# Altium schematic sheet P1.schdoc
size 594 x 419 mm; Symbol: Drawing-Symbol_A4; Company: 嘉立创EDA; Version: V1.0; Page Size: A4; @Project Name: mairui N1; @Update Date: 2026-05-10; @Create Date: 2026-05-10; Device: Drawing-Symbol_A4; @Board Name: 底板_2; @Page Name: P1; @Create Time: 14:56:52; @Page Count: 6; @Page No: 6; @Schematic Name: Bottom_4; @Update Time: 14:56:52; @Assembly Variant: Basic; Border: 1; Title Block Position: 3; Size: A4; Width: 2338; Height: 1652; Region Start: 1; X Region Count: 6; Y Region Count: 4; Blade Width: 10
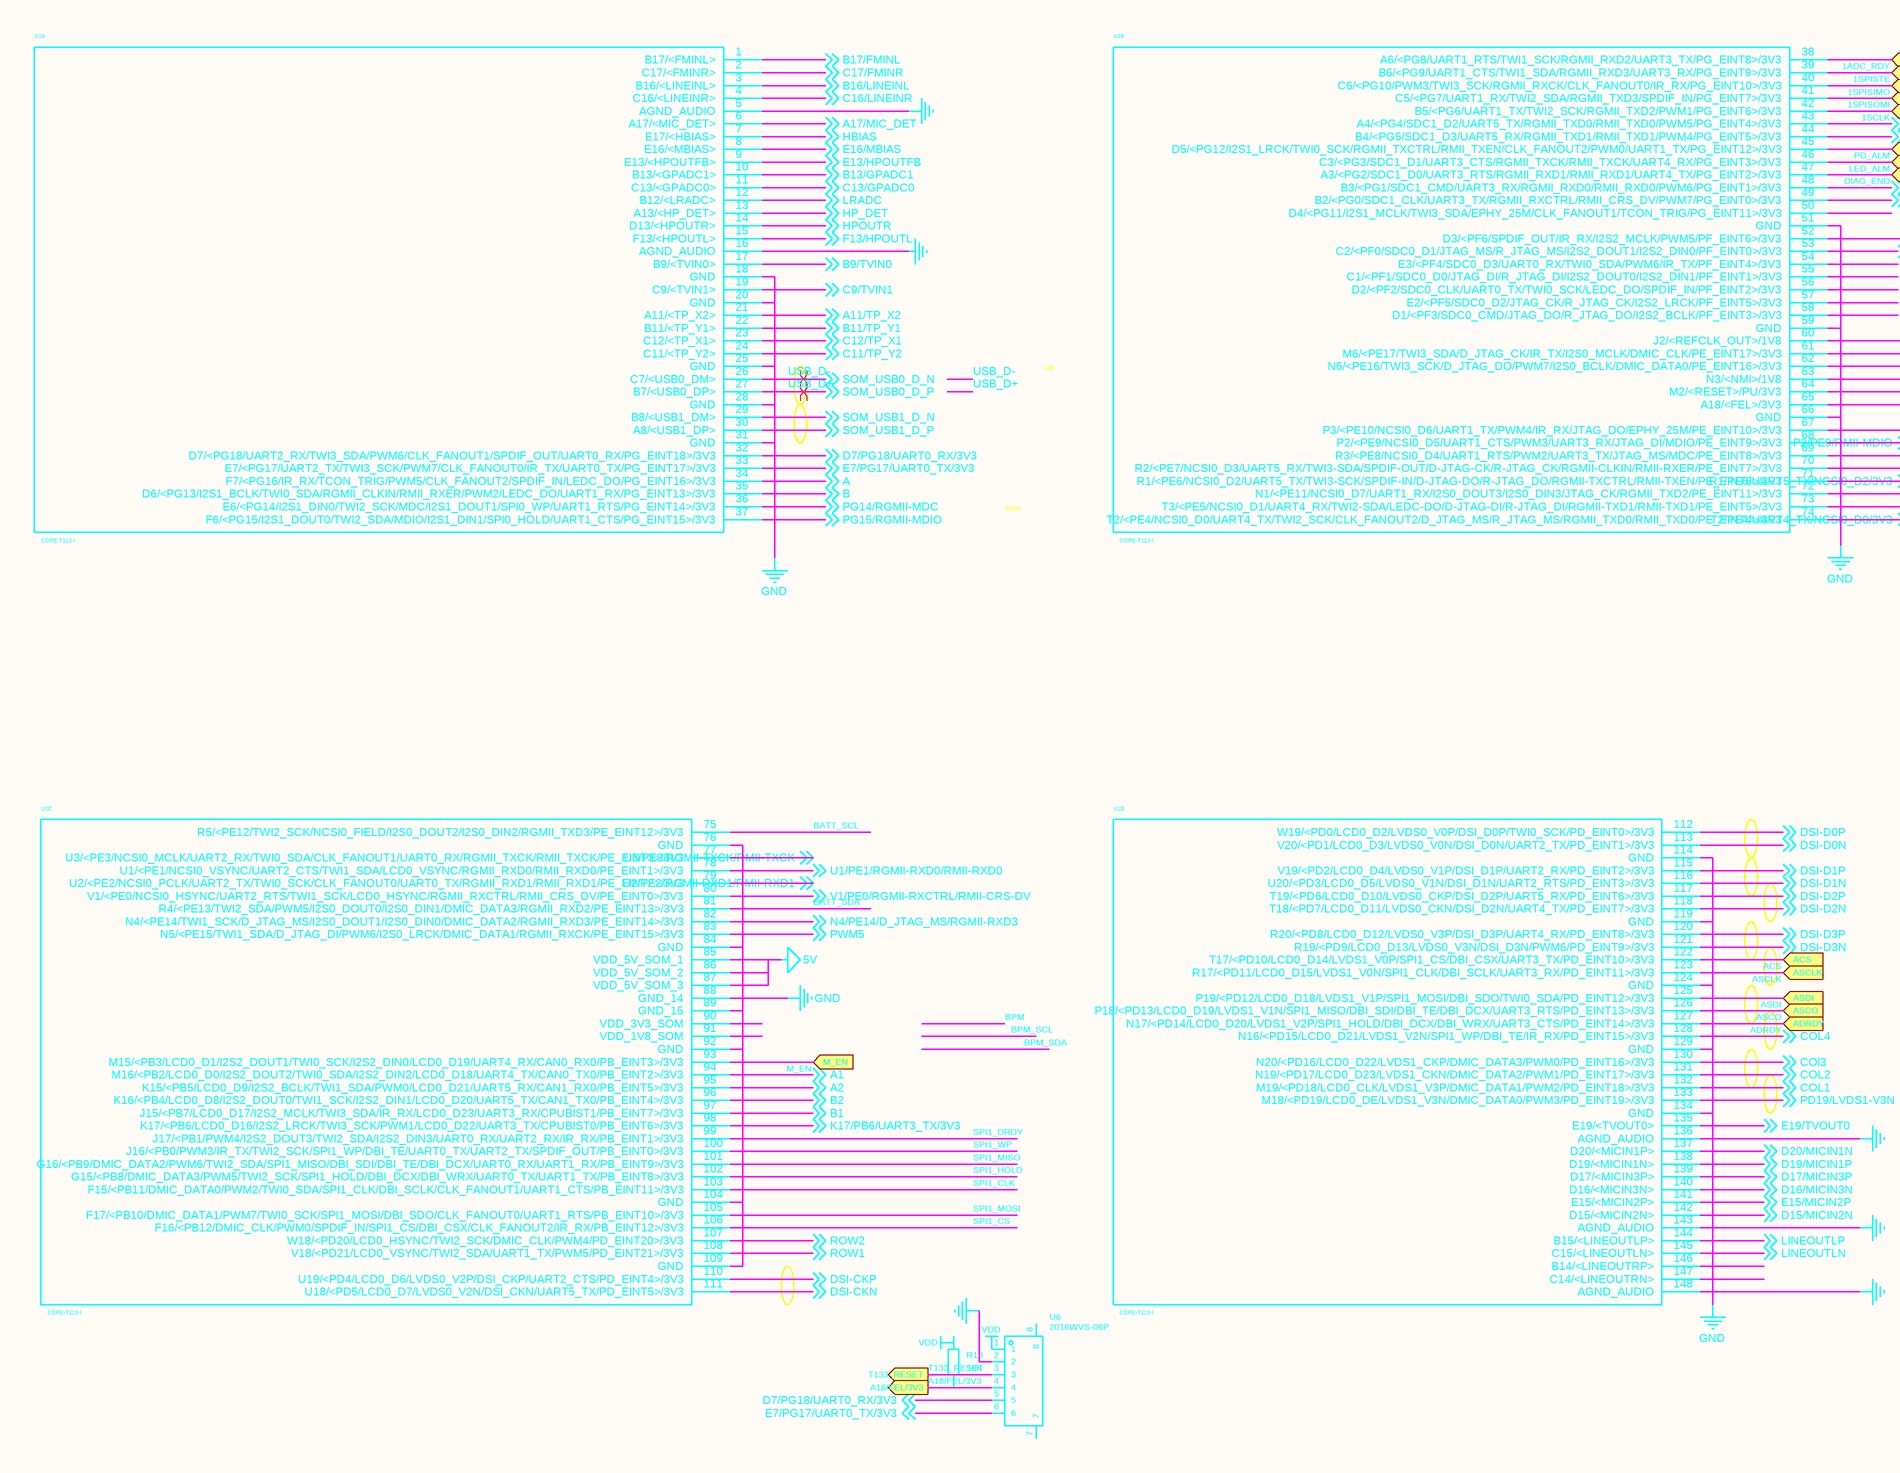
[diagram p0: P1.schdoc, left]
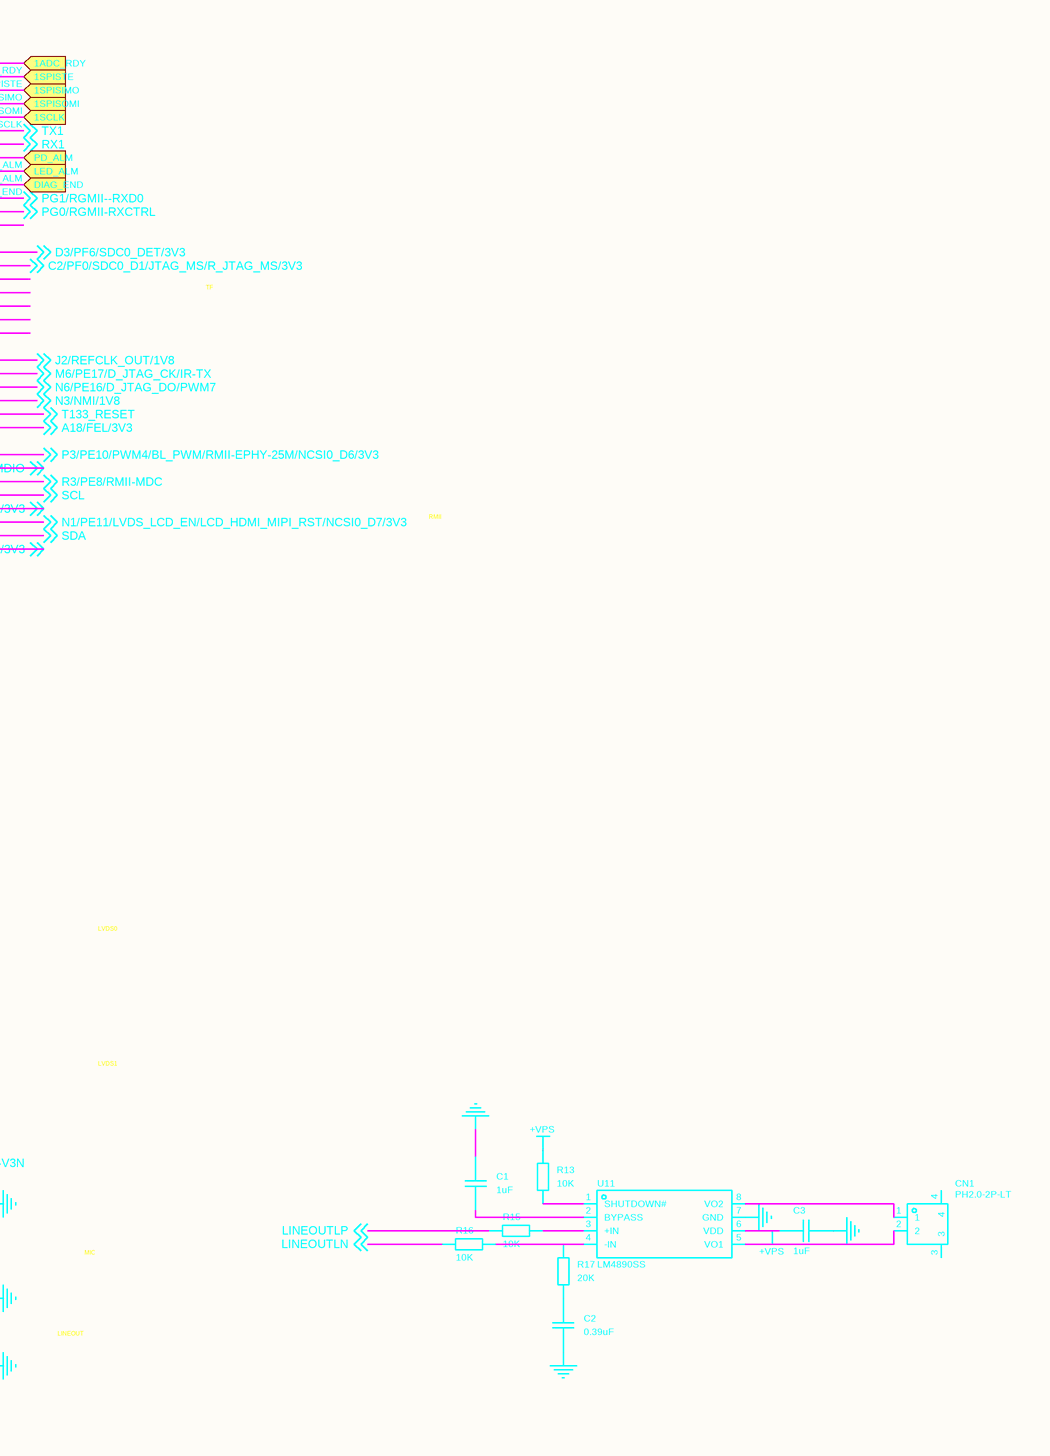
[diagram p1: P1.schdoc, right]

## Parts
C1  1uF  [C0603]
C2  0.39uF  [C0603]
C3  1uF  [C0603]
CN1  PH2.0-2P-LT  [CONN-SMD_PH2.0-1X2PW]
R13  10K  [R0603]
R15  10K  [R0603]
R16  10K  [R0603]
R17  20K  [R0603]
R18  10K  [R0603]
U1  CORE-T113-I  [CORE-40X40-TAP148]  (parts A,B,C,D of 4)
U6  2016WVS-06P  [CONN-SMD_2016WVS-06P]
U11  LM4890SS  [MSOP-8_L3.0-W3.0-P0.65-LS4.9-BL-1]

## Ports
1ADC_RDY (in), 1SCLK (in), 1SPISIMO (in), 1SPISOMI (in), 1SPISTE (in), A18/FEL/3V3 (out), ACS (in), ADRDY (in), ASCLK (in), ASCO (in), ASDI (in), DIAG_END (in), LED_ALM (in), M_EN (in), PD_ALM (in), T133_RESET (out)

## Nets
5V: U1.85(VDD_5V_SOM_1) U1.86(VDD_5V_SOM_2) U1.87(VDD_5V_SOM_3)
+VPS: C3.2 R13.2 U11.6(VDD)
GND: C1.2 C2.2 C3.1 U1.5(AGND_AUDIO) U1.16(AGND_AUDIO) U1.18(GND) U1.20(GND) U1.25(GND) U1.28(GND) U1.31(GND) U1.51(GND) U1.59(GND) U1.66(GND) U1.76(GND) U1.84(GND) U1.88(GND_14) U1.89(GND_15) U1.92(GND) U1.104(GND) U1.109(GND) U1.114(GND) U1.119(GND) U1.124(GND) U1.129(GND) U1.134(GND) U1.136(AGND_AUDIO) U1.143(AGND_AUDIO) U1.148(AGND_AUDIO) U6.2 U11.7(GND)
VDD: U6.1
1ADC_RDY: U1.38(A6/<PG8/UART1_RTS/TWI1_SCK/RGMII_RXD2/UART3_TX/PG_EINT8>/3V3) ; port 1ADC_RDY
1SCLK: U1.42(B5/<PG6/UART1_TX/TWI2_SCK/RGMII_TXD2/PWM1/PG_EINT6>/3V3) ; port 1SCLK
1SPISIMO: U1.40(C6/<PG10/PWM3/TWI3_SCK/RGMII_RXCK/CLK_FANOUT0/IR_RX/PG_EINT10>/3V3) ; port 1SPISIMO
1SPISOMI: U1.41(C5/<PG7/UART1_RX/TWI2_SDA/RGMII_TXD3/SPDIF_IN/PG_EINT7>/3V3) ; port 1SPISOMI
1SPISTE: U1.39(B6/<PG9/UART1_CTS/TWI1_SDA/RGMII_RXD3/UART3_RX/PG_EINT9>/3V3) ; port 1SPISTE
A: U1.34(F7/<PG16/IR_RX/TCON_TRIG/PWM5/CLK_FANOUT2/SPDIF_IN/LEDC_DO/PG_EINT16>/3V3) ; off-sheet A
A1: U1.94(M16/<PB2/LCD0_D0/I2S2_DOUT2/TWI0_SDA/I2S2_DIN2/LCD0_D18/UART4_TX/CAN0_TX0/PB_EINT2>/3V3) ; off-sheet A1
A2: U1.95(K15/<PB5/LCD0_D9/I2S2_BCLK/TWI1_SDA/PWM0/LCD0_D21/UART5_RX/CAN1_RX0/PB_EINT5>/3V3) ; off-sheet A2
A11/TP_X2: U1.21(A11/<TP_X2>) ; off-sheet A11/TP_X2
A17/MIC_DET: U1.6(A17/<MIC_DET>) ; off-sheet A17/MIC_DET
A18/FEL/3V3: R18.1 U1.65(A18/<FEL>/3V3) U6.4 ; off-sheet A18/FEL/3V3, port A18/FEL/3V3
ACS: U1.122(T17/<PD10/LCD0_D14/LVDS1_V0P/SPI1_CS/DBI_CSX/UART3_TX/PD_EINT10>/3V3) ; port ACS
ADRDY: U1.127(N17/<PD14/LCD0_D20/LVDS1_V2P/SPI1_HOLD/DBI_DCX/DBI_WRX/UART3_CTS/PD_EINT14>/3V3) ; port ADRDY
ASCLK: U1.123(R17/<PD11/LCD0_D15/LVDS1_V0N/SPI1_CLK/DBI_SCLK/UART3_RX/PD_EINT11>/3V3) ; port ASCLK
ASCO: U1.126(P18/<PD13/LCD0_D19/LVDS1_V1N/SPI1_MISO/DBI_SDI/DBI_TE/DBI_DCX/UART3_RTS/PD_EINT13>/3V3) ; port ASCO
ASDI: U1.125(P19/<PD12/LCD0_D18/LVDS1_V1P/SPI1_MOSI/DBI_SDO/TWI0_SDA/PD_EINT12>/3V3) ; port ASDI
B: U1.35(D6/<PG13/I2S1_BCLK/TWI0_SDA/RGMII_CLKIN/RMII_RXER/PWM2/LEDC_DO/UART1_RX/PG_EINT13>/3V3) ; off-sheet B
B1: U1.97(J15/<PB7/LCD0_D17/I2S2_MCLK/TWI3_SDA/IR_RX/LCD0_D23/UART3_RX/CPUBIST1/PB_EINT7>/3V3) ; off-sheet B1
B2: U1.96(K16/<PB4/LCD0_D8/I2S2_DOUT0/TWI1_SCK/I2S2_DIN1/LCD0_D20/UART5_TX/CAN1_TX0/PB_EINT4>/3V3) ; off-sheet B2
B9/TVIN0: U1.17(B9/<TVIN0>) ; off-sheet B9/TVIN0
B11/TP_Y1: U1.22(B11/<TP_Y1>) ; off-sheet B11/TP_Y1
B13/GPADC1: U1.10(B13/<GPADC1>) ; off-sheet B13/GPADC1
B16/LINEINL: U1.3(B16/<LINEINL>) ; off-sheet B16/LINEINL
B17/FMINL: U1.1(B17/<FMINL>) ; off-sheet B17/FMINL
BATT_SCL: U1.75(R5/<PE12/TWI2_SCK/NCSI0_FIELD/I2S0_DOUT2/I2S0_DIN2/RGMII_TXD3/PE_EINT12>/3V3)
BATT_SDA: U1.81(R4/<PE13/TWI2_SDA/PWM5/I2S0_DOUT0/I2S0_DIN1/DMIC_DATA3/RGMII_RXD2/PE_EINT13>/3V3)
C2/PF0/SDC0_D1/JTAG_MS/R_JTAG_MS/3V3: U1.53(C2/<PF0/SDC0_D1/JTAG_MS/R_JTAG_MS/I2S2_DOUT1/I2S2_DIN0/PF_EINT0>/3V3) ; off-sheet C2/PF0/SDC0_D1/JTAG_MS/R_JTAG_MS/3V3
C9/TVIN1: U1.19(C9/<TVIN1>) ; off-sheet C9/TVIN1
C11/TP_Y2: U1.24(C11/<TP_Y2>) ; off-sheet C11/TP_Y2
C12/TP_X1: U1.23(C12/<TP_X1>) ; off-sheet C12/TP_X1
C13/GPADC0: U1.11(C13/<GPADC0>) ; off-sheet C13/GPADC0
C16/LINEINR: U1.4(C16/<LINEINR>) ; off-sheet C16/LINEINR
C17/FMINR: U1.2(C17/<FMINR>) ; off-sheet C17/FMINR
COL1: U1.132(M19/<PD18/LCD0_CLK/LVDS1_V3P/DMIC_DATA1/PWM2/PD_EINT18>/3V3) ; off-sheet COL1
COL2: U1.131(N19/<PD17/LCD0_D23/LVDS1_CKN/DMIC_DATA2/PWM1/PD_EINT17>/3V3) ; off-sheet COL2
COl3: U1.130(N20/<PD16/LCD0_D22/LVDS1_CKP/DMIC_DATA3/PWM0/PD_EINT16>/3V3) ; off-sheet COl3
COL4: U1.128(N16/<PD15/LCD0_D21/LVDS1_V2N/SPI1_WP/DBI_TE/IR_RX/PD_EINT15>/3V3) ; off-sheet COL4
D3/PF6/SDC0_DET/3V3: U1.52(D3/<PF6/SPDIF_OUT/IR_RX/I2S2_MCLK/PWM5/PF_EINT6>/3V3) ; off-sheet D3/PF6/SDC0_DET/3V3
D7/PG18/UART0_RX/3V3: U1.32(D7/<PG18/UART2_RX/TWI3_SDA/PWM6/CLK_FANOUT1/SPDIF_OUT/UART0_RX/PG_EINT18>/3V3) U6.5 ; off-sheet D7/PG18/UART0_RX/3V3
D15/MICIN2N: U1.142(D15/<MICIN2N>) ; off-sheet D15/MICIN2N
D16/MICIN3N: U1.140(D16/<MICIN3N>) ; off-sheet D16/MICIN3N
D17/MICIN3P: U1.139(D17/<MICIN3P>) ; off-sheet D17/MICIN3P
D19/MICIN1P: U1.138(D19/<MICIN1N>) ; off-sheet D19/MICIN1P
D20/MICIN1N: U1.137(D20/<MICIN1P>) ; off-sheet D20/MICIN1N
DIAG_END: U1.47(A3/<PG2/SDC1_D0/UART3_RTS/RGMII_RXD1/RMII_RXD1/UART4_TX/PG_EINT2>/3V3) ; port DIAG_END
DSI-CKN: U1.111(U18/<PD5/LCD0_D7/LVDS0_V2N/DSI_CKN/UART5_TX/PD_EINT5>/3V3) ; off-sheet DSI-CKN
DSI-CKP: U1.110(U19/<PD4/LCD0_D6/LVDS0_V2P/DSI_CKP/UART2_CTS/PD_EINT4>/3V3) ; off-sheet DSI-CKP
DSI-D0N: U1.113(V20/<PD1/LCD0_D3/LVDS0_V0N/DSI_D0N/UART2_TX/PD_EINT1>/3V3) ; off-sheet DSI-D0N
DSI-D0P: U1.112(W19/<PD0/LCD0_D2/LVDS0_V0P/DSI_D0P/TWI0_SCK/PD_EINT0>/3V3) ; off-sheet DSI-D0P
DSI-D1N: U1.116(U20/<PD3/LCD0_D5/LVDS0_V1N/DSI_D1N/UART2_RTS/PD_EINT3>/3V3) ; off-sheet DSI-D1N
DSI-D1P: U1.115(V19/<PD2/LCD0_D4/LVDS0_V1P/DSI_D1P/UART2_RX/PD_EINT2>/3V3) ; off-sheet DSI-D1P
DSI-D2N: U1.118(T18/<PD7/LCD0_D11/LVDS0_CKN/DSI_D2N/UART4_TX/PD_EINT7>/3V3) ; off-sheet DSI-D2N
DSI-D2P: U1.117(T19/<PD6/LCD0_D10/LVDS0_CKP/DSI_D2P/UART5_RX/PD_EINT6>/3V3) ; off-sheet DSI-D2P
DSI-D3N: U1.121(R19/<PD9/LCD0_D13/LVDS0_V3N/DSI_D3N/PWM6/PD_EINT9>/3V3) ; off-sheet DSI-D3N
DSI-D3P: U1.120(R20/<PD8/LCD0_D12/LVDS0_V3P/DSI_D3P/UART4_RX/PD_EINT8>/3V3) ; off-sheet DSI-D3P
E7/PG17/UART0_TX/3V3: U1.33(E7/<PG17/UART2_TX/TWI3_SCK/PWM7/CLK_FANOUT0/IR_TX/UART0_TX/PG_EINT17>/3V3) U6.6 ; off-sheet E7/PG17/UART0_TX/3V3
E13/HPOUTFB: U1.9(E13/<HPOUTFB>) ; off-sheet E13/HPOUTFB
E15/MICIN2P: U1.141(E15/<MICIN2P>) ; off-sheet E15/MICIN2P
E16/MBIAS: U1.8(E16/<MBIAS>) ; off-sheet E16/MBIAS
E19/TVOUT0: U1.135(E19/<TVOUT0>) ; off-sheet E19/TVOUT0
F13/HPOUTL: U1.15(F13/<HPOUTL>) ; off-sheet F13/HPOUTL
HBIAS: U1.7(E17/<HBIAS>) ; off-sheet HBIAS
HP_DET: U1.13(A13/<HP_DET>) ; off-sheet HP_DET
HPOUTR: U1.14(D13/<HPOUTR>) ; off-sheet HPOUTR
J2/REFCLK_OUT/1V8: U1.60(J2/<REFCLK_OUT>/1V8) ; off-sheet J2/REFCLK_OUT/1V8
K17/PB6/UART3_TX/3V3: U1.98(K17/<PB6/LCD0_D16/I2S2_LRCK/TWI3_SCK/PWM1/LCD0_D22/UART3_TX/CPUBIST0/PB_EINT6>/3V3) ; off-sheet K17/PB6/UART3_TX/3V3
LED_ALM: U1.46(C3/<PG3/SDC1_D1/UART3_CTS/RGMII_TXCK/RMII_TXCK/UART4_RX/PG_EINT3>/3V3) ; port LED_ALM
LINEOUTLN: R16.1 U1.145(C15/<LINEOUTLN>) ; off-sheet LINEOUTLN
LINEOUTLP: R15.1 U1.144(B15/<LINEOUTLP>) ; off-sheet LINEOUTLP
LRADC: U1.12(B12/<LRADC>) ; off-sheet LRADC
M6/PE17/D_JTAG_CK/IR-TX: U1.61(M6/<PE17/TWI3_SDA/D_JTAG_CK/IR_TX/I2S0_MCLK/DMIC_CLK/PE_EINT17>/3V3) ; off-sheet M6/PE17/D_JTAG_CK/IR-TX
M_EN: U1.93(M15/<PB3/LCD0_D1/I2S2_DOUT1/TWI0_SCK/I2S2_DIN0/LCD0_D19/UART4_RX/CAN0_RX0/PB_EINT3>/3V3) ; port M_EN
N1/PE11/LVDS_LCD_EN/LCD_HDMI_MIPI_RST/NCSI0_D7/3V3: U1.72(N1/<PE11/NCSI0_D7/UART1_RX/I2S0_DOUT3/I2S0_DIN3/JTAG_CK/RGMII_TXD2/PE_EINT11>/3V3) ; off-sheet N1/PE11/LVDS_LCD_EN/LCD_HDMI_MIPI_RST/NCSI0_D7/3V3
N3/NMI/1V8: U1.63(N3/<NMI>/1V8) ; off-sheet N3/NMI/1V8
N4/PE14/D_JTAG_MS/RGMII-RXD3: U1.82(N4/<PE14/TWI1_SCK/D_JTAG_MS/I2S0_DOUT1/I2S0_DIN0/DMIC_DATA2/RGMII_RXD3/PE_EINT14>/3V3) ; off-sheet N4/PE14/D_JTAG_MS/RGMII-RXD3
N6/PE16/D_JTAG_DO/PWM7: U1.62(N6/<PE16/TWI3_SCK/D_JTAG_DO/PWM7/I2S0_BCLK/DMIC_DATA0/PE_EINT16>/3V3) ; off-sheet N6/PE16/D_JTAG_DO/PWM7
P2/PE9/RMII-MDIO: U1.68(P2/<PE9/NCSI0_D5/UART1_CTS/PWM3/UART3_RX/JTAG_DI/MDIO/PE_EINT9>/3V3) ; off-sheet P2/PE9/RMII-MDIO
P3/PE10/PWM4/BL_PWM/RMII-EPHY-25M/NCSI0_D6/3V3: U1.67(P3/<PE10/NCSI0_D6/UART1_TX/PWM4/IR_RX/JTAG_DO/EPHY_25M/PE_EINT10>/3V3) ; off-sheet P3/PE10/PWM4/BL_PWM/RMII-EPHY-25M/NCSI0_D6/3V3
PD19/LVDS1-V3N: U1.133(M18/<PD19/LCD0_DE/LVDS1_V3N/DMIC_DATA0/PWM3/PD_EINT19>/3V3) ; off-sheet PD19/LVDS1-V3N
PD_ALM: U1.45(D5/<PG12/I2S1_LRCK/TWI0_SCK/RGMII_TXCTRL/RMII_TXEN/CLK_FANOUT2/PWM0/UART1_TX/PG_EINT12>/3V3) ; port PD_ALM
PG0/RGMII-RXCTRL: U1.49(B2/<PG0/SDC1_CLK/UART3_TX/RGMII_RXCTRL/RMII_CRS_DV/PWM7/PG_EINT0>/3V3) ; off-sheet PG0/RGMII-RXCTRL
PG1/RGMII--RXD0: U1.48(B3/<PG1/SDC1_CMD/UART3_RX/RGMII_RXD0/RMII_RXD0/PWM6/PG_EINT1>/3V3) ; off-sheet PG1/RGMII--RXD0
PG14/RGMII-MDC: U1.36(E6/<PG14/I2S1_DIN0/TWI2_SCK/MDC/I2S1_DOUT1/SPI0_WP/UART1_RTS/PG_EINT14>/3V3) ; off-sheet PG14/RGMII-MDC
PG15/RGMII-MDIO: U1.37(F6/<PG15/I2S1_DOUT0/TWI2_SDA/MDIO/I2S1_DIN1/SPI0_HOLD/UART1_CTS/PG_EINT15>/3V3) ; off-sheet PG15/RGMII-MDIO
PWM5: U1.83(N5/<PE15/TWI1_SDA/D_JTAG_DI/PWM6/I2S0_LRCK/DMIC_DATA1/RGMII_RXCK/PE_EINT15>/3V3) ; off-sheet PWM5
R1/PE6/UART5_TX/NCSI0_D2/3V3: U1.71(R1/<PE6/NCSI0_D2/UART5_TX/TWI3-SCK/SPDIF-IN/D-JTAG-DO/R-JTAG_DO/RGMII-TXCTRL/RMII-TXEN/PE_EINT6>/3V3) ; off-sheet R1/PE6/UART5_TX/NCSI0_D2/3V3
R3/PE8/RMII-MDC: U1.69(R3/<PE8/NCSI0_D4/UART1_RTS/PWM2/UART3_TX/JTAG_MS/MDC/PE_EINT8>/3V3) ; off-sheet R3/PE8/RMII-MDC
ROW1: U1.108(V18/<PD21/LCD0_VSYNC/TWI2_SDA/UART1_TX/PWM5/PD_EINT21>/3V3) ; off-sheet ROW1
ROW2: U1.107(W18/<PD20/LCD0_HSYNC/TWI2_SCK/DMIC_CLK/PWM4/PD_EINT20>/3V3) ; off-sheet ROW2
RX1: U1.44(B4/<PG5/SDC1_D3/UART5_RX/RGMII_TXD1/RMII_TXD1/PWM4/PG_EINT5>/3V3) ; off-sheet RX1
SCL: U1.70(R2/<PE7/NCSI0_D3/UART5_RX/TWI3-SDA/SPDIF-OUT/D-JTAG-CK/R-JTAG_CK/RGMII-CLKIN/RMII-RXER/PE_EINT7>/3V3) ; off-sheet SCL
SDA: U1.73(T3/<PE5/NCSI0_D1/UART4_RX/TWI2-SDA/LEDC-DO/D-JTAG-DI/R-JTAG_DI/RGMII-TXD1/RMII-TXD1/PE_EINT5>/3V3) ; off-sheet SDA
SOM_USB1_D_N: U1.29(B8/<USB1_DM>) ; off-sheet SOM_USB1_D_N
SOM_USB1_D_P: U1.30(A8/<USB1_DP>) ; off-sheet SOM_USB1_D_P
SPI1_CLK: U1.103(F15/<PB11/DMIC_DATA0/PWM2/TWI0_SDA/SPI1_CLK/DBI_SCLK/CLK_FANOUT1/UART1_CTS/PB_EINT11>/3V3)
SPI1_CS: U1.106(F16/<PB12/DMIC_CLK/PWM0/SPDIF_IN/SPI1_CS/DBI_CSX/CLK_FANOUT2/IR_RX/PB_EINT12>/3V3)
SPI1_DRDY: U1.99(J17/<PB1/PWM4/I2S2_DOUT3/TWI2_SDA/I2S2_DIN3/UART0_RX/UART2_RX/IR_RX/PB_EINT1>/3V3)
SPI1_HOLD: U1.102(G15/<PB8/DMIC_DATA3/PWM5/TWI2_SCK/SPI1_HOLD/DBI_DCX/DBI_WRX/UART0_TX/UART1_TX/PB_EINT8>/3V3)
SPI1_MISO: U1.101(G16/<PB9/DMIC_DATA2/PWM6/TWI2_SDA/SPI1_MISO/DBI_SDI/DBI_TE/DBI_DCX/UART0_RX/UART1_RX/PB_EINT9>/3V3)
SPI1_MOSI: U1.105(F17/<PB10/DMIC_DATA1/PWM7/TWI0_SCK/SPI1_MOSI/DBI_SDO/CLK_FANOUT0/UART1_RTS/PB_EINT10>/3V3)
SPI1_WP: U1.100(J16/<PB0/PWM3/IR_TX/TWI2_SCK/SPI1_WP/DBI_TE/UART0_TX/UART2_TX/SPDIF_OUT/PB_EINT0>/3V3)
T2/PE4/UART4_TX/NCSI0_D0/3V3: U1.74(T2/<PE4/NCSI0_D0/UART4_TX/TWI2_SCK/CLK_FANOUT2/D_JTAG_MS/R_JTAG_MS/RGMII_TXD0/RMII_TXD0/PE_EINT4>/3V3) ; off-sheet T2/PE4/UART4_TX/NCSI0_D0/3V3
T133_RESET: U1.64(M2/<RESET>/PU/3V3) U6.3 ; off-sheet T133_RESET, port T133_RESET
TX1: U1.43(A4/<PG4/SDC1_D2/UART5_TX/RGMII_TXD0/RMII_TXD0/PWM5/PG_EINT4>/3V3) ; off-sheet TX1
U1/PE1/RGMII-RXD0/RMII-RXD0: U1.78(U1/<PE1/NCSI0_VSYNC/UART2_CTS/TWI1_SDA/LCD0_VSYNC/RGMII_RXD0/RMII_RXD0/PE_EINT1>/3V3) ; off-sheet U1/PE1/RGMII-RXD0/RMII-RXD0
U2/PE2/RGMII-RXD1/RMII-RXD1: U1.79(U2/<PE2/NCSI0_PCLK/UART2_TX/TWI0_SCK/CLK_FANOUT0/UART0_TX/RGMII_RXD1/RMII_RXD1/PE_EINT2>/3V3) ; off-sheet U2/PE2/RGMII-RXD1/RMII-RXD1
U3/PE3/RGMII-TXCK/RMII-TXCK: U1.77(U3/<PE3/NCSI0_MCLK/UART2_RX/TWI0_SDA/CLK_FANOUT1/UART0_RX/RGMII_TXCK/RMII_TXCK/PE_EINT3>/3V3) ; off-sheet U3/PE3/RGMII-TXCK/RMII-TXCK
USB_D+: U1.27(B7/<USB0_DP>) ; off-sheet SOM_USB0_D_P  [also labelled SOM_USB0_D_P]
USB_D-: U1.26(C7/<USB0_DM>) ; off-sheet SOM_USB0_D_N  [also labelled SOM_USB0_D_N]
V1/PE0/RGMII-RXCTRL/RMII-CRS-DV: U1.80(V1/<PE0/NCSI0_HSYNC/UART2_RTS/TWI1_SCK/LCD0_HSYNC/RGMII_RXCTRL/RMII_CRS_DV/PE_EINT0>/3V3) ; off-sheet V1/PE0/RGMII-RXCTRL/RMII-CRS-DV
NetC1_1: C1.1 U11.2(BYPASS)
NetC2_1: C2.1 R17.2
NetCN1_1: CN1.1 U11.8(VO2)
NetCN1_2: CN1.2 U11.5(VO1)
NetR13_1: R13.1 U11.1(SHUTDOWN#)
NetR15_2: R15.2 U11.3(+IN)
NetR16_2: R16.2 R17.1 U11.4(-IN)

Not connected (* = marked no-connect by the designer): CN1 3 4; R18 2; U1 50(D4/<PG11/I2S1_MCLK/TWI3_SDA/EPHY_25M/CLK_FANOUT1/TCON_TRIG/PG_EINT11>/3V3) 54(E3/<PF4/SDC0_D3/UART0_RX/TWI0_SDA/PWM6/IR_TX/PF_EINT4>/3V3) 55(C1/<PF1/SDC0_D0/JTAG_DI/R_JTAG_DI/I2S2_DOUT0/I2S2_DIN1/PF_EINT1>/3V3) 56(D2/<PF2/SDC0_CLK/UART0_TX/TWI0_SCK/LEDC_DO/SPDIF_IN/PF_EINT2>/3V3) 57(E2/<PF5/SDC0_D2/JTAG_CK/R_JTAG_CK/I2S2_LRCK/PF_EINT5>/3V3) 58(D1/<PF3/SDC0_CMD/JTAG_DO/R_JTAG_DO/I2S2_BCLK/PF_EINT3>/3V3) 90(VDD_3V3_SOM) 91(VDD_1V8_SOM) 146(B14/<LINEOUTRP>) 147(C14/<LINEOUTRN>); U6 7 8

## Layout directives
differential pair; Symbol: DIFFPAIR; Device: DIFFPAIR; Comment: DIFFPAIR; differential pair; Add into BOM: yes: USB_D+, USB_D-

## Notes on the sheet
- TF
- USB
- RGMII
- RMII
- LVDS0
- LVDS1
- MIC
- LINEOUT
- Labels drawn without touching a wire or pin: VDD

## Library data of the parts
C1-C3 = CAP_0603: Symbol: Capacitance; 3D Model: ac125912035d415993ca9572d50418b1; 3D Model Transform: 62.992,31.496,0,0,0,0,0,0,0; ConvertToPcb: yes; ModelName: C0603_L1.6-W0.8-H0.8
CN1 = PH2.0-2P-LT: 插针结构:1x2P;间距:2mm;安装方式:立贴;参考系列:-;总PIN数:2P;排数:1;每排PIN数:2;行距:-;额定电流:-;触头材质:黄铜;触头镀层:锡;工作温度:-;; Manufacturer: CAX(创都); AddInBom: yes; ModelId: 8fc0578891594ccb901fd2caad40de010819f05c4eef4c71ace90d822a990e87; ModelTransform: 314.96,291.338,0,180,0,0,0,40.435,0; Pins Structure: 1x2P; Pitch: 2mm; Number of PINs Per Row: 2; Plastic Material: LCP; Flame Retardant Rating: UL94V-0; Z-Height of the Board: 6.5mm; X-Length of Bottom Edge on Board (Spacing Line): 8mm; Y-Width of Bottom Edge on Board: 5.4mm
R13 R15-R18 = Res_0603: Symbol: 电阻; 3D Model: fc143cca1e79419f9cd78b61e9279f08; 3D Model Transform: 31.8897,63.7794,0,90,0,0,0,0,0; ConvertToPcb: yes
U1 = CORE-T113-I: Relevance: []; SPLIT_INST: TRUE; SWAP_INFO: (S1+S2+S3+S4); Origin Footprint: SMD_140P_45x35; AddInBom: yes
U6 = 2016WVS-06P: 插针结构:1x6P;间距:2mm;安装方式:立贴;参考系列:PH;总PIN数:6P;排数:1;每排PIN数:6;触头材质:黄铜;触头镀层:锡;; Manufacturer: HanElectricity(瀚源); AddInBom: yes; ModelId: f56667f1f58343dab0a571e340e733d20819f05c4eef4c71ace90d822a990e87; ModelTransform: 625.983,279.9207,0,0,0,0,0,-8.15,0; Pins Structure: 1x6P; Pitch: 2mm; Reference Series: PH; Number of PINs Per Row: 6; Plastic Material: LCP; Flame Retardant Rating: UL94V-0; Z-Height of the Board: 6.2mm; Y-Width of Bottom Edge on Board: 5.4mm
U11 = LM4890SS: 功放类型:AB类功放;扬声器通道数:-;输出功率:1.3Wx1@8Ω;静态电流(Iq):9mA;; Manufacturer: IDCHIP(英锐芯); 3D Model: 374647af99ae41c4bb682bd336d5e4ed0819f05c4eef4c71ace90d822a990e87; 3D Model Transform: 118.11,192.913,0,0,0,0,0,0,0; Class: AB类功放; Total Harmonic Distortion + Noise (THD+N): 1%; Quiescent Current: 9mA; Power Supply Rejection Ratio (PSRR): 85dB；90dB; Voltage - Supply: 2.5V~5.5V; AddInBom: yes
